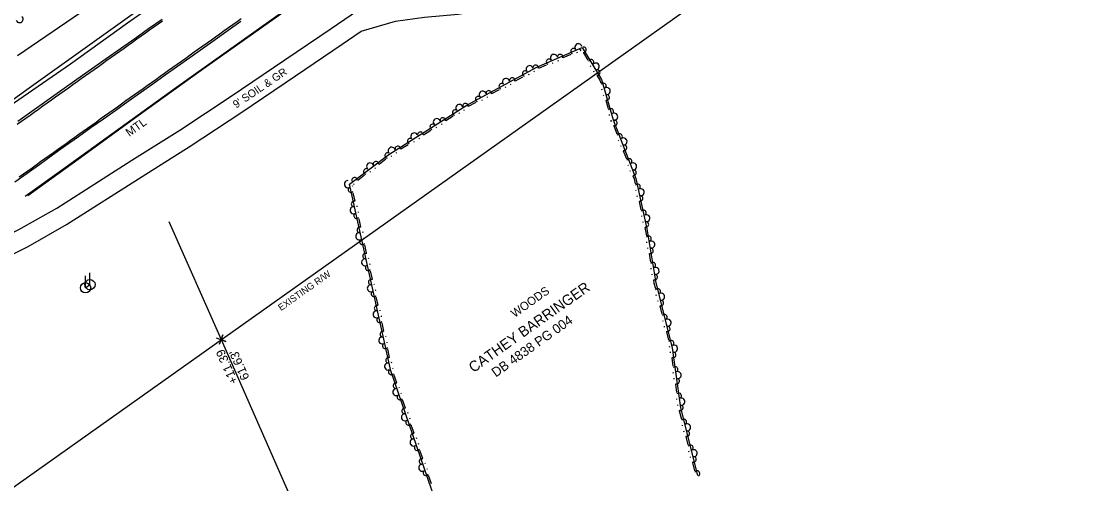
# Model space of a CAD drawing. Extents: x 1577032 to 1581865, y 611492 to 615011.
# Drawn here: x 1579290 to 1579794, y 612819 to 613040 of the extents above; entities that cross this region are included whole.
import ezdxf

# ---------------------------------------------------------------- set-up
doc = ezdxf.new("R2010")
doc.units = 0
for name, color, linetype in [('Exist Guardrail', 7, 'Continuous'), ('Exist Guardrail Text', 7, 'Continuous'), ('Exist Hydro Jurisdictional Stream or Body of Water', 7, 'Continuous'), ('Exist Property Corner CELL', 7, 'Continuous'), ('Exist Property Deed Book Text', 7, 'Continuous'), ('Exist Property Line', 7, 'Continuous'), ('Exist Property Owner Text', 7, 'Continuous'), ('Exist Property Tie Line', 7, 'Continuous'), ('Exist Property Tie Line Text', 7, 'Continuous'), ('Exist Right of Way Line', 7, 'Continuous'), ('Exist Right of Way Line Text', 7, 'Continuous'), ('Exist Roads EOP', 7, 'Continuous'), ('Exist Roads EOT', 7, 'Continuous'), ('Exist Utilities Power Pole CELL', 7, 'Continuous'), ('Exist Vegetation Woods Line Text', 7, 'Continuous'), ('Old_Level_11', 7, 'Continuous'), ('Old_Level_7', 7, 'Continuous'), ('Scratch_Level_4', 7, 'Continuous')]:
    doc.layers.add(name, color=color, linetype=linetype)

msp = doc.modelspace()

# ---------------------------------------------------------------- linework, layer by layer
at = {"layer": 'Exist Guardrail'}
for points in [[(1579741.96, 613283.96), (1579737.12, 613281.13), (1579730.57, 613276.73), (1579719.79, 613268.84), (1579713.42, 613263.83), (1579705.29, 613256.98), (1579695.7, 613249.06), (1579686.81, 613242.18), (1579647.6, 613212.65), (1579618.22, 613190.29), (1579587.73, 613167.25), (1579572.92, 613156.39), (1579515.84, 613115.84), (1579461.27, 613076.76), (1579417.23, 613045.78), (1579363.89, 613007.87), (1579309.01, 612968.33), (1579291.73, 612955.85)], [(1579270.82, 612990.01), (1579282.03, 612997.58), (1579313.36, 613019.2), (1579340.57, 613038.66), (1579350.53, 613045.77), (1579360.58, 613053.18), (1579373.08, 613062.65), (1579398.99, 613080.9), (1579432.12, 613104.02), (1579469.62, 613130.21), (1579505.56, 613155.76), (1579562.8, 613196.46), (1579596.52, 613220.88), (1579629.59, 613245.26)]]:
    msp.add_lwpolyline(points, dxfattribs=at)
at = {"layer": 'Exist Hydro Jurisdictional Stream or Body of Water'}
msp.add_lwpolyline([(1579288.2, 613023.08), (1579321.6, 613045.97), (1579377.92, 613086.65), (1579397.8, 613103.82), (1579505.23, 613183.74), (1579586.29, 613243.39)], dxfattribs=at)
at = {"layer": 'Exist Property Corner CELL'}
msp.add_line((1579385.12, 612887.69), (1579385.12, 612887.69), dxfattribs=at)
msp.add_lwpolyline([(1579382.79, 612888.59), (1579387.45, 612886.78), (1579385.12, 612887.69), (1579386.02, 612890.02), (1579384.21, 612885.36)], dxfattribs=at)
at = {"layer": 'Exist Property Line'}
msp.add_line((1579385.12, 612887.69), (1579705.74, 612159.89), dxfattribs=at)
at = {"layer": 'Exist Property Tie Line'}
msp.add_line((1579360.27, 612944.08), (1579385.12, 612887.69), dxfattribs=at)
at = {"layer": 'Exist Right of Way Line'}
msp.add_line((1578304.92, 612120.6), (1580458.22, 613649.74), dxfattribs=at)
at = {"layer": 'Exist Roads EOP'}
for points in [[(1579286.83, 612962.85), (1579292.74, 612967.06), (1579298.75, 612971.34), (1579304.86, 612975.72), (1579311.03, 612980.17), (1579317.13, 612984.52), (1579323.11, 612988.75), (1579329.04, 612992.93), (1579334.95, 612997.11), (1579340.84, 613001.3), (1579346.73, 613005.49), (1579352.61, 613009.67), (1579358.49, 613013.86), (1579364.38, 613018.05), (1579370.28, 613022.25), (1579376.26, 613026.51), (1579382.33, 613030.83), (1579388.43, 613035.18), (1579394.54, 613039.52)], [(1579357, 613040.34), (1579350.61, 613035.79), (1579343.98, 613031.09), (1579337.24, 613026.34), (1579330.38, 613021.52), (1579323.41, 613016.61), (1579316.35, 613011.62), (1579309.22, 613006.57), (1579302.08, 613001.51), (1579294.98, 612996.48), (1579288.28, 612991.71)]]:
    msp.add_lwpolyline(points, dxfattribs=at)
at = {"layer": 'Exist Roads EOT'}
for points in [[(1579357.18, 613039.56), (1579355.15, 613038.11), (1579353.11, 613036.66), (1579351.08, 613035.21), (1579349.04, 613033.76), (1579347.01, 613032.3), (1579344.97, 613030.85), (1579342.94, 613029.4), (1579340.9, 613027.95), (1579338.87, 613026.5), (1579336.83, 613025.05), (1579334.8, 613023.59), (1579332.76, 613022.14), (1579330.73, 613020.69), (1579328.69, 613019.24), (1579326.66, 613017.79), (1579324.62, 613016.33), (1579322.59, 613014.88), (1579320.55, 613013.43), (1579318.52, 613011.98), (1579316.48, 613010.53), (1579314.45, 613009.08), (1579312.41, 613007.62), (1579310.37, 613006.17), (1579308.34, 613004.72), (1579306.3, 613003.27), (1579304.27, 613001.82), (1579302.23, 613000.37), (1579300.2, 612998.91), (1579298.16, 612997.46), (1579296.13, 612996.01), (1579294.1, 612994.55), (1579292.07, 612993.1), (1579290.03, 612991.65), (1579288, 612990.19)], [(1579288.95, 612965.25), (1579290.98, 612966.71), (1579293.01, 612968.16), (1579295.05, 612969.62), (1579297.08, 612971.07), (1579299.11, 612972.53), (1579301.15, 612973.98), (1579303.18, 612975.43), (1579305.21, 612976.89), (1579307.25, 612978.34), (1579309.28, 612979.8), (1579311.31, 612981.25), (1579313.35, 612982.71), (1579315.38, 612984.16), (1579317.41, 612985.61), (1579319.44, 612987.07), (1579321.48, 612988.52), (1579323.51, 612989.98), (1579325.54, 612991.43), (1579327.58, 612992.89), (1579329.61, 612994.34), (1579331.64, 612995.79), (1579333.68, 612997.25), (1579335.71, 612998.7), (1579337.74, 613000.16), (1579339.78, 613001.61), (1579341.81, 613003.06), (1579343.85, 613004.51), (1579345.88, 613005.96), (1579347.92, 613007.41), (1579349.96, 613008.87), (1579351.99, 613010.32), (1579354.03, 613011.77), (1579356.06, 613013.22), (1579358.1, 613014.67), (1579360.13, 613016.12), (1579362.17, 613017.57), (1579364.2, 613019.03), (1579366.24, 613020.48), (1579368.27, 613021.93), (1579370.31, 613023.38), (1579372.34, 613024.83), (1579374.38, 613026.28), (1579376.41, 613027.73), (1579378.45, 613029.19), (1579380.49, 613030.64), (1579382.52, 613032.09), (1579384.56, 613033.54), (1579386.59, 613034.99), (1579388.63, 613036.44), (1579390.67, 613037.89), (1579392.7, 613039.34), (1579394.74, 613040.78)]]:
    msp.add_lwpolyline(points, dxfattribs=at)
at = {"layer": 'Exist Utilities Power Pole CELL'}
for p, q in [((1579320.54, 612912.41), (1579320.54, 612918.03)), ((1579322.66, 612913.91), (1579322.66, 612919.54)), ((1579320.54, 612912.41), (1579322.66, 612913.91)), ((1579322.66, 612913.91), (1579322.66, 612913.91)), ((1579320.54, 612912.41), (1579320.54, 612912.41))]:
    msp.add_line(p, q, dxfattribs=at)
for centre in [(1579320.54, 612912.41), (1579322.66, 612913.91)]:
    msp.add_circle(centre, 2.45, dxfattribs=at)
at = {"layer": 'Old_Level_11'}
for points in [[(1579508.7, 612724.29), (1579492.44, 612795.6), (1579465.98, 612872.85), (1579446.35, 612961.85), (1579465.03, 612975.91), (1579502.24, 612999.44), (1579535.51, 613017.56), (1579557.11, 613026.95), (1579566.37, 613011.68), (1579571.95, 612992.54), (1579582.68, 612964.52), (1579588.02, 612940.44), (1579592.16, 612914.79), (1579600.03, 612883.86), (1579603.93, 612855.11), (1579612.08, 612822.98)], [(1579548.08, 613022.13), (1579551.85, 613023.76)], [(1579554.64, 613024.53), (1579555.02, 613024.7)], [(1579556.62, 613025.39), (1579556.09, 613026.27)], [(1579557.72, 613024.38), (1579559.84, 613020.87)], [(1579536.43, 613017.06), (1579540.19, 613018.7)], [(1579542.98, 613019.46), (1579543.36, 613019.63)], [(1579545.62, 613020.61), (1579545.99, 613020.77)], [(1579531.62, 613014.04), (1579531.98, 613014.23)], [(1579534.14, 613015.41), (1579534.5, 613015.61)], [(1579560.98, 613018.2), (1579561.19, 613017.85)], [(1579562.47, 613015.75), (1579562.68, 613015.4)], [(1579564.31, 613013.51), (1579565.62, 613011.35), (1579566, 613010.04)], [(1579522.97, 613009.33), (1579523.33, 613009.53)], [(1579525.3, 613011.06), (1579528.9, 613013.03)], [(1579511.81, 613003.25), (1579512.17, 613003.45)], [(1579514.13, 613004.99), (1579517.74, 613006.95)], [(1579520.45, 613007.96), (1579520.81, 613008.15)], [(1579566.41, 613007.17), (1579566.52, 613006.78)], [(1579567.21, 613004.42), (1579567.32, 613004.02)], [(1579502.97, 612998.91), (1579506.57, 613000.87)], [(1579509.29, 613001.88), (1579509.65, 613002.08)], [(1579568.41, 613001.77), (1579569.55, 612997.84)], [(1579492.26, 612992.16), (1579495.72, 612994.35)], [(1579498.37, 612995.54), (1579498.72, 612995.76)], [(1579500.79, 612997.07), (1579501.14, 612997.29)], [(1579569.96, 612994.97), (1579570.08, 612994.57)], [(1579487.62, 612988.74), (1579487.97, 612988.96)], [(1579490.05, 612990.28), (1579490.4, 612990.5)], [(1579570.76, 612992.24), (1579570.78, 612992.16), (1579570.94, 612991.73)], [(1579572.21, 612989.58), (1579573.67, 612985.75)], [(1579479.3, 612983.48), (1579479.65, 612983.7)], [(1579481.51, 612985.37), (1579484.98, 612987.56)], [(1579470.77, 612978.57), (1579474.23, 612980.76)], [(1579476.88, 612981.95), (1579477.22, 612982.17)], [(1579574.32, 612982.92), (1579574.46, 612982.54)], [(1579575.34, 612980.24), (1579575.49, 612979.86)], [(1579460.37, 612971.38), (1579463.65, 612973.85)], [(1579466.13, 612975.16), (1579466.48, 612975.37)], [(1579468.56, 612976.69), (1579468.91, 612976.91)], [(1579576.75, 612977.71), (1579578.22, 612973.88)], [(1579458.33, 612969.33), (1579458.66, 612969.58)], [(1579578.86, 612971.05), (1579579.01, 612970.67)], [(1579579.89, 612968.37), (1579580.04, 612967.99)], [(1579450.22, 612963.74), (1579453.49, 612966.2)], [(1579456.03, 612967.6), (1579456.36, 612967.85)], [(1579581.3, 612965.84), (1579581.9, 612964.28), (1579582.4, 612962.02)], [(1579447.88, 612960.64), (1579447.79, 612961.04)], [(1579448.17, 612961.69), (1579448.5, 612961.93)], [(1579582.62, 612959.13), (1579582.71, 612958.73)], [(1579448.98, 612953.74), (1579448.1, 612957.74)], [(1579583.24, 612956.33), (1579583.33, 612955.93)], [(1579584.26, 612953.61), (1579585.15, 612949.61)], [(1579450, 612951.02), (1579449.91, 612951.42)], [(1579450.61, 612948.22), (1579450.53, 612948.62)], [(1579451.72, 612941.33), (1579450.83, 612945.33)], [(1579585.37, 612946.72), (1579585.46, 612946.32)], [(1579585.99, 612943.92), (1579586.08, 612943.52)], [(1579452.74, 612938.61), (1579452.65, 612939.01)], [(1579587.02, 612941.2), (1579587.22, 612940.29), (1579587.71, 612937.21)], [(1579453.35, 612935.81), (1579453.26, 612936.21)], [(1579454.45, 612928.91), (1579453.57, 612932.92)], [(1579587.77, 612934.31), (1579587.83, 612933.91)], [(1579588.22, 612931.48), (1579588.29, 612931.07)], [(1579589.08, 612928.71), (1579589.74, 612924.66)], [(1579455.47, 612926.2), (1579455.38, 612926.6)], [(1579456.09, 612923.39), (1579456, 612923.79)], [(1579457.19, 612916.5), (1579456.31, 612920.5)], [(1579589.79, 612921.76), (1579589.85, 612921.35)], [(1579590.25, 612918.93), (1579590.31, 612918.52)], [(1579458.21, 612913.78), (1579458.12, 612914.18)], [(1579591.11, 612916.16), (1579591.35, 612914.62), (1579592, 612912.08)], [(1579458.83, 612910.98), (1579458.74, 612911.38)], [(1579459.93, 612904.08), (1579459.05, 612908.09)], [(1579592.31, 612909.2), (1579592.41, 612908.8)], [(1579593.02, 612906.42), (1579593.12, 612906.02)], [(1579594.12, 612903.74), (1579595.14, 612899.76)], [(1579460.95, 612901.37), (1579460.86, 612901.77)], [(1579461.57, 612898.56), (1579461.48, 612898.96)], [(1579462.67, 612891.67), (1579461.79, 612895.67)], [(1579595.45, 612896.88), (1579595.55, 612896.48)], [(1579596.15, 612894.1), (1579596.25, 612893.7)], [(1579463.69, 612888.95), (1579463.6, 612889.35)], [(1579597.26, 612891.42), (1579598.27, 612887.44)], [(1579464.31, 612886.15), (1579464.22, 612886.55)], [(1579465.41, 612879.25), (1579464.52, 612883.26)], [(1579598.58, 612884.56), (1579598.68, 612884.16)], [(1579599.06, 612881.88), (1579599.11, 612881.47)], [(1579599.85, 612879.09), (1579600.4, 612875.02)], [(1579466.43, 612876.54), (1579466.34, 612876.94)], [(1579467.04, 612873.73), (1579466.96, 612874.13)], [(1579468.81, 612867.12), (1579467.48, 612871)], [(1579600.38, 612872.12), (1579600.44, 612871.72)], [(1579600.77, 612869.28), (1579600.82, 612868.87)], [(1579470.13, 612864.54), (1579469.99, 612864.92)], [(1579601.56, 612866.49), (1579602.11, 612862.42)], [(1579471.06, 612861.82), (1579470.92, 612862.21)], [(1579472.93, 612855.09), (1579471.6, 612858.97)], [(1579602.09, 612859.52), (1579602.15, 612859.12)], [(1579474.25, 612852.51), (1579474.11, 612852.9)], [(1579602.48, 612856.68), (1579602.53, 612856.27)], [(1579603.41, 612853.82), (1579604.42, 612849.85)], [(1579475.18, 612849.79), (1579475.04, 612850.18)], [(1579477.05, 612843.06), (1579475.72, 612846.94)], [(1579604.73, 612846.96), (1579604.83, 612846.57)], [(1579605.44, 612844.18), (1579605.54, 612843.78)], [(1579478.37, 612840.48), (1579478.23, 612840.87)], [(1579479.3, 612837.77), (1579479.16, 612838.15)], [(1579606.54, 612841.5), (1579607.55, 612837.53)], [(1579481.17, 612831.04), (1579479.84, 612834.92)], [(1579607.86, 612834.64), (1579607.96, 612834.24)], [(1579482.49, 612828.45), (1579482.35, 612828.84)], [(1579608.56, 612831.86), (1579608.66, 612831.46)], [(1579609.67, 612829.18), (1579610.67, 612825.2)], [(1579483.42, 612825.74), (1579483.28, 612826.13)], [(1579485.29, 612819.01), (1579483.96, 612822.89)]]:
    msp.add_lwpolyline(points, dxfattribs=at)
for centre, radius, start, end in [((1579289.14, 613040.49), 1.69, 201.3241, 49.3966), ((1579555.33, 613027.07), 1.69, 9.4605, 217.533), ((1579543.67, 613022), 1.69, 9.4605, 217.533), ((1579546.63, 613022.39), 1.3, 344.2652, 185.0618), ((1579553.02, 613025.17), 1.3, 41.9317, 242.7283), ((1579557.78, 613025.86), 1.3, 262.0071, 102.8037), ((1579534.99, 613017.28), 1.3, 349.3347, 190.1313), ((1579541.36, 613020.1), 1.3, 41.9317, 242.7283), ((1579561.39, 613019.89), 1.3, 319.6736, 160.4702), ((1579563.58, 613017.87), 1.69, 287.2024, 135.2749), ((1579529.95, 613014.53), 1.3, 47.0012, 247.7977), ((1579532.08, 613016.62), 1.69, 14.53, 222.6025), ((1579564.37, 613014.99), 1.3, 262.0071, 102.8037), ((1579518.78, 613008.45), 1.3, 47.0012, 247.7977), ((1579520.91, 613010.54), 1.69, 14.53, 222.6025), ((1579523.83, 613011.2), 1.3, 349.3347, 190.1313), ((1579567.24, 613008.7), 1.3, 304.6705, 145.467), ((1579507.62, 613002.37), 1.3, 47.0012, 247.7977), ((1579509.75, 613004.46), 1.69, 14.53, 222.6025), ((1579512.66, 613005.12), 1.3, 349.3347, 190.1313), ((1579568.83, 613006.17), 1.69, 272.1993, 120.2717), ((1579568.85, 613003.19), 1.3, 247.004, 87.8006), ((1579498.66, 612998.15), 1.69, 18.271, 226.3435), ((1579501.52, 612998.99), 1.3, 353.0758, 193.8723), ((1579490.78, 612992.2), 1.3, 353.0758, 193.8723), ((1579496.67, 612995.92), 1.3, 50.7422, 251.5388), ((1579570.8, 612996.49), 1.3, 304.6705, 145.467), ((1579572.39, 612993.96), 1.69, 272.1993, 120.2717), ((1579485.93, 612989.13), 1.3, 50.7422, 251.5388), ((1579487.91, 612991.35), 1.69, 18.271, 226.3435), ((1579572.53, 612991.02), 1.3, 251.7301, 92.5267), ((1579475.18, 612982.33), 1.3, 50.7422, 251.5388), ((1579477.17, 612984.56), 1.69, 18.271, 226.3435), ((1579480.03, 612985.4), 1.3, 353.0758, 193.8723), ((1579575.02, 612984.51), 1.3, 309.3966, 150.1931), ((1579576.82, 612982.12), 1.69, 276.9254, 124.9979), ((1579466.42, 612977.77), 1.69, 18.271, 226.3435), ((1579469.29, 612978.61), 1.3, 353.0758, 193.8723), ((1579577.08, 612979.15), 1.3, 251.7301, 92.5267), ((1579464.47, 612975.49), 1.3, 55.3969, 256.1935), ((1579579.57, 612972.64), 1.3, 309.3966, 150.1931), ((1579454.31, 612967.85), 1.3, 55.3969, 256.1935), ((1579456.11, 612970.23), 1.69, 22.9257, 230.9982), ((1579458.9, 612971.3), 1.3, 357.7304, 198.527), ((1579581.37, 612970.25), 1.69, 276.9254, 124.9979), ((1579581.63, 612967.28), 1.3, 251.7301, 92.5267), ((1579445.52, 612961.8), 1.69, 88.4015, 296.474), ((1579448.74, 612963.65), 1.3, 357.7304, 198.527), ((1579446.94, 612959.17), 1.3, 120.8727, 321.6693), ((1579583.55, 612960.6), 1.3, 300.9394, 141.7359), ((1579584.98, 612957.97), 1.69, 268.4682, 116.5407), ((1579448.44, 612952.36), 1.3, 63.2062, 264.0028), ((1579584.8, 612954.99), 1.3, 243.2729, 84.0695), ((1579448.26, 612949.38), 1.69, 88.4015, 296.474), ((1579586.31, 612948.19), 1.3, 300.9394, 141.7359), ((1579449.68, 612946.76), 1.3, 120.8727, 321.6693), ((1579587.73, 612945.56), 1.69, 268.4682, 116.5407), ((1579587.55, 612942.58), 1.3, 243.2729, 84.0695), ((1579451, 612936.97), 1.69, 88.4015, 296.474), ((1579451.18, 612939.95), 1.3, 63.2062, 264.0028), ((1579452.42, 612934.34), 1.3, 120.8727, 321.6693), ((1579588.78, 612935.72), 1.3, 297.5904, 138.387), ((1579590.05, 612933.02), 1.69, 265.1192, 113.1917), ((1579453.92, 612927.53), 1.3, 63.2062, 264.0028), ((1579589.7, 612930.05), 1.3, 239.9239, 80.7205), ((1579453.74, 612924.55), 1.69, 88.4015, 296.474), ((1579455.15, 612921.93), 1.3, 120.8727, 321.6693), ((1579590.81, 612923.17), 1.3, 297.5904, 138.387), ((1579591.72, 612917.5), 1.3, 239.9239, 80.7205), ((1579592.07, 612920.47), 1.69, 265.1192, 113.1917), ((1579456.47, 612912.14), 1.69, 88.4015, 296.474), ((1579456.66, 612915.12), 1.3, 63.2062, 264.0028), ((1579457.89, 612909.51), 1.3, 120.8727, 321.6693), ((1579593.2, 612910.7), 1.3, 302.7094, 143.5059), ((1579594.7, 612908.12), 1.69, 270.2382, 118.3107), ((1579459.39, 612902.7), 1.3, 63.2062, 264.0028), ((1579594.62, 612905.13), 1.3, 245.0429, 85.8395), ((1579459.21, 612899.72), 1.69, 88.4015, 296.474), ((1579460.63, 612897.1), 1.3, 120.8727, 321.6693), ((1579596.33, 612898.38), 1.3, 302.7094, 143.5059), ((1579597.84, 612895.8), 1.69, 270.2382, 118.3107), ((1579597.75, 612892.81), 1.3, 245.0429, 85.8395), ((1579461.95, 612887.31), 1.69, 88.4015, 296.474), ((1579462.13, 612890.29), 1.3, 63.2062, 264.0028), ((1579463.37, 612884.68), 1.3, 120.8727, 321.6693), ((1579599.47, 612886.05), 1.3, 302.7094, 143.5059), ((1579600.92, 612883.37), 1.69, 263.6971, 111.7696), ((1579464.87, 612877.87), 1.3, 63.2062, 264.0028), ((1579600.5, 612880.41), 1.3, 238.5018, 79.2984), ((1579464.69, 612874.89), 1.69, 88.4015, 296.474), ((1579466.17, 612872.28), 1.3, 127.344, 328.1406), ((1579601.43, 612873.51), 1.3, 296.1683, 136.9649), ((1579602.63, 612870.77), 1.69, 263.6971, 111.7696), ((1579602.21, 612867.82), 1.3, 238.5018, 79.2984), ((1579468.59, 612862.71), 1.69, 94.8728, 302.9453), ((1579468.43, 612865.69), 1.3, 69.6776, 270.4741), ((1579470.29, 612860.26), 1.3, 127.344, 328.1406), ((1579603.14, 612860.91), 1.3, 296.1683, 136.9649), ((1579604.34, 612858.17), 1.69, 263.6971, 111.7696), ((1579472.71, 612850.68), 1.69, 94.8728, 302.9453), ((1579472.55, 612853.66), 1.3, 69.6776, 270.4741), ((1579603.92, 612855.22), 1.3, 238.5018, 79.2984), ((1579474.41, 612848.23), 1.3, 127.344, 328.1406), ((1579605.62, 612848.46), 1.3, 302.673, 143.4696), ((1579607.12, 612845.88), 1.69, 270.2019, 118.2743), ((1579476.67, 612841.64), 1.3, 69.6776, 270.4741), ((1579607.03, 612842.89), 1.3, 245.0066, 85.8032), ((1579476.83, 612838.65), 1.69, 94.8728, 302.9453), ((1579478.53, 612836.2), 1.3, 127.344, 328.1406), ((1579608.75, 612836.14), 1.3, 302.673, 143.4696), ((1579610.25, 612833.56), 1.69, 270.2019, 118.2743), ((1579480.95, 612826.63), 1.69, 94.8728, 302.9453), ((1579480.79, 612829.61), 1.3, 69.6776, 270.4741), ((1579610.16, 612830.57), 1.3, 245.0066, 85.8032), ((1579482.65, 612824.18), 1.3, 127.344, 328.1406), ((1579611.87, 612823.81), 1.3, 302.673, 143.4696)]:
    msp.add_arc(centre, radius, start, end, dxfattribs=at)
at = {"layer": 'Old_Level_7'}
for points in [[(1579270.48, 612991.08), (1579293.75, 613007.73), (1579350.33, 613048.3), (1579401.47, 613085.17), (1579429.06, 613103.98), (1579472.86, 613133.85), (1579536.14, 613178.58), (1579588.49, 613216.36), (1579619.01, 613238.99)], [(1579633.23, 613200.96), (1579607.11, 613180.86), (1579580.36, 613161.21), (1579524.24, 613121.13), (1579478.41, 613088.53), (1579436.79, 613059.35), (1579401.7, 613034.42), (1579375.63, 613015.91), (1579345.59, 612994.44), (1579319.84, 612975.64), (1579293.12, 612956.3)]]:
    msp.add_lwpolyline(points, dxfattribs=at)
at = {"layer": 'Scratch_Level_4'}
for points in [[(1579257.08, 612930.28), (1579261.41, 612929.35), (1579264.24, 612929.29), (1579266.84, 612929.7), (1579275.85, 612933.66), (1579288.81, 612940.24), (1579306.8, 612950.42), (1579342.67, 612973.2), (1579365.44, 612987.62), (1579389.96, 613003.82), (1579415.46, 613021.09), (1579437.57, 613036.08), (1579459.69, 613051.21), (1579481.01, 613065.74), (1579505.4, 613082.19), (1579529.67, 613096.91), (1579552.94, 613111.78), (1579575.12, 613126.05), (1579598.2, 613139.02), (1579618.96, 613150.59), (1579636.68, 613161.23), (1579642.25, 613164.38)], [(1579451.91, 613034.73), (1579468.26, 613039.44), (1579482.07, 613041.37), (1579497.99, 613042.91), (1579516.69, 613045.82), (1579536.3, 613047.71), (1579555.14, 613051.48), (1579576.28, 613058.16), (1579597.1, 613064.65), (1579614.52, 613068.29)], [(1579255.16, 612921.3), (1579260.74, 612920.11), (1579265.37, 612920.02), (1579269.05, 612920.64), (1579279.78, 612925.35), (1579293.15, 612932.14), (1579311.53, 612942.54), (1579347.59, 612965.45), (1579370.43, 612979.91), (1579395.07, 612996.19), (1579420.61, 613013.48), (1579442.74, 613028.49), (1579451.93, 613034.78)]]:
    msp.add_lwpolyline(points, dxfattribs=at)

# ---------------------------------------------------------------- texts
at = {"layer": 'Exist Guardrail Text'}
msp.add_text('MTL', height=4, rotation=35.7712, dxfattribs=at).set_placement((1579341.41, 612984.27))
at = {"layer": 'Exist Property Deed Book Text'}
msp.add_text('DB 4838 PG 004', height=4.5, rotation=35.38, dxfattribs=at).set_placement((1579516, 612869.61))
at = {"layer": 'Exist Property Owner Text'}
msp.add_text('CATHEY BARRINGER', height=5, rotation=35.38, dxfattribs=at).set_placement((1579505.34, 612871.73))
at = {"layer": 'Exist Property Tie Line Text'}
for s, p in [('+11.39', (1579393.31, 612867.65)), ("61.63'", (1579398.73, 612869.48))]:
    msp.add_text(s, height=4.2, rotation=113.7751, dxfattribs=at).set_placement(p)
at = {"layer": 'Exist Right of Way Line Text'}
msp.add_text('EXISTING R/W', height=3.2, rotation=35.38, dxfattribs=at).set_placement((1579413.67, 612901.24))
at = {"layer": 'Exist Vegetation Woods Line Text'}
msp.add_text('WOODS', height=4, rotation=35.38, dxfattribs=at).set_placement((1579524.99, 612898.03))
at = {"layer": 'Scratch_Level_4'}
msp.add_text("9' SOIL & GR", height=3.6909, rotation=34.0977, dxfattribs=at).set_placement((1579392.32, 612997.82))

doc.saveas('drawing.dxf')
